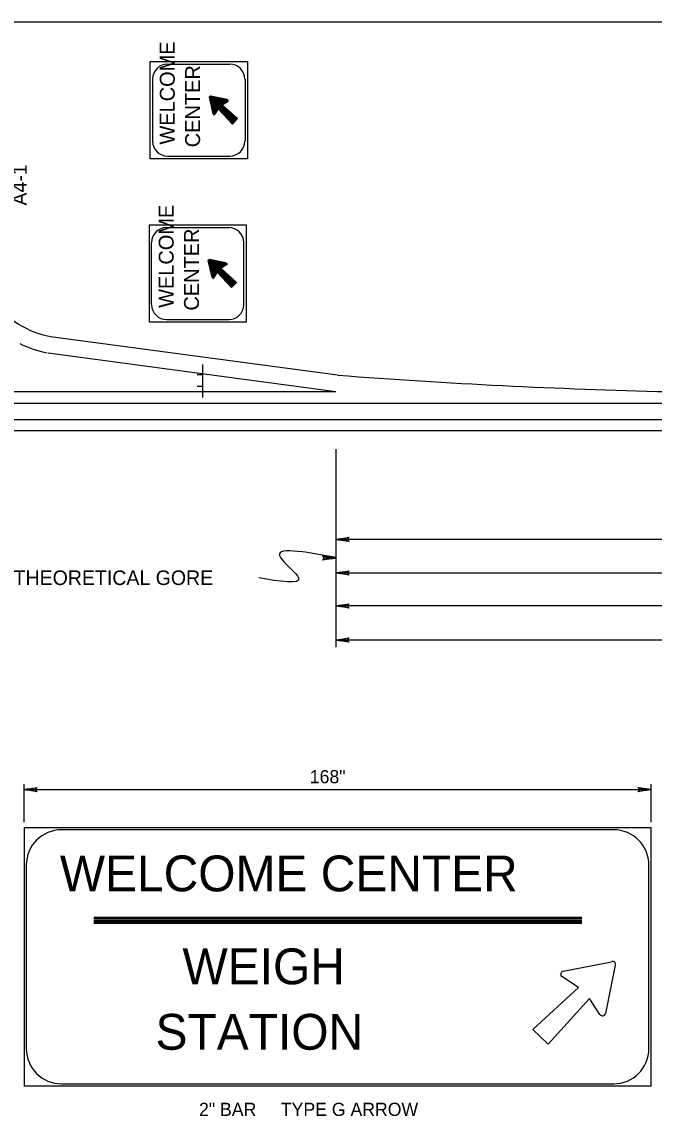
# Model space of a CAD drawing. Extents: x 638689 to 652291, y 298458 to 299646.
# Drawn here: x 651609.3 to 651753, y 298788 to 299036.7 of the extents above; entities that cross this region are included whole.
import ezdxf

# ---------------------------------------------------------------- set-up
doc = ezdxf.new("R2010")
doc.units = 0
for name, color, linetype in [('1', 7, 'Continuous'), ('2', 7, 'Continuous'), ('3', 7, 'Continuous')]:
    doc.layers.add(name, color=color, linetype=linetype)

# ---------------------------------------------------------------- blocks, each defined once
blk = doc.blocks.new('RARROW')
at = {"layer": '3'}
blk.add_lwpolyline([(-2.2695, 0.285), (-2.184875, 0.12075), (0, 0), (-2.2695, 0.285), (-2.38575, 0.384625), (0, 0), (-2.183125, -0.108), (-2.262875, -0.2705), (0, 0), (-2.38575, -0.379125), (-2.262875, -0.2705)], dxfattribs=at)

msp = doc.modelspace()

# ---------------------------------------------------------------- linework, layer by layer
at = {"layer": '1'}
msp.add_line((651426.31, 299036.75), (652212.31, 299036.75), dxfattribs=at)
at = {"layer": '2'}
for p, q in [((651642.44, 299027.12), (651656.56, 299027.12)), ((651651.81, 299019.87), (651651.81, 299019.87)), ((651655.94, 299019.12), (651652.19, 299019.87)), ((651651.94, 299019.62), (651652.81, 299015.87)), ((651654.81, 299017.87), (651656.19, 299018.75)), ((651654.81, 299017.87), (651654.81, 299017.87)), ((651658.31, 299014.75), (651654.81, 299017.87)), ((651656.56, 299019), (651656.56, 299019)), ((651652.94, 299015.37), (651652.94, 299015.37)), ((651653.19, 299015.75), (651653.94, 299017)), ((651653.94, 299017), (651653.94, 299017)), ((651653.94, 299017), (651657.19, 299013.5)), ((651657.19, 299013.5), (651658.31, 299014.75)), ((651660.56, 299005.62), (651638.44, 299005.62)), ((651656.56, 299006.12), (651642.44, 299006.12)), ((651642.19, 298990), (651656.44, 298990)), ((651651.56, 298982.75), (651651.56, 298982.75)), ((651651.69, 298982.5), (651652.56, 298978.75)), ((651655.69, 298982), (651651.94, 298982.75)), ((651652.94, 298978.62), (651653.69, 298979.87)), ((651653.69, 298979.87), (651653.69, 298979.87)), ((651653.69, 298979.87), (651656.94, 298976.37)), ((651654.56, 298980.75), (651655.81, 298981.62)), ((651654.56, 298980.75), (651654.56, 298980.75)), ((651658.06, 298977.5), (651654.56, 298980.75)), ((651656.31, 298981.87), (651656.31, 298981.87)), ((651652.69, 298978.25), (651652.69, 298978.25)), ((651656.94, 298976.37), (651658.06, 298977.5)), ((651660.31, 298968.5), (651638.31, 298968.5)), ((651656.44, 298969), (651642.19, 298969)), ((651615.81, 298965.25), (651681.06, 298956.5)), ((651615.31, 298961.5), (651615.31, 298961.5)), ((651615.31, 298961.5), (651680.69, 298952.75)), ((651650.44, 298951.37), (651650.44, 298958.87)), ((651650.44, 298956.5), (651649.19, 298956.5)), ((651441.81, 298952.75), (651680.69, 298952.75)), ((651650.44, 298953.87), (651649.19, 298953.87)), ((651680.69, 298952.75), (651680.69, 298952.75)), ((651680.69, 298952.75), (651680.69, 298952.75)), ((651429.31, 298950.12), (652211.31, 298950.12)), ((651429.31, 298946.37), (652211.31, 298946.37)), ((651429.31, 298943.87), (652211.31, 298943.87)), ((651680.69, 298939.62), (651680.69, 298894.62)), ((651917.06, 298919.12), (651680.69, 298919.12)), ((651680.69, 298911.5), (652031.94, 298911.5)), ((652084.69, 298904), (651680.69, 298904)), ((652137.56, 298896.25), (651680.69, 298896.25)), ((651609.82, 298854.87), (651609.82, 298863.49)), ((651752.32, 298854.87), (651752.32, 298863.49)), ((651609.82, 298862.24), (651752.32, 298862.24)), ((651609.82, 298853.62), (651752.32, 298853.62)), ((651609.82, 298853.62), (651609.82, 298794.87)), ((651743.82, 298853.12), (651618.32, 298853.12)), ((651752.32, 298794.87), (651752.32, 298853.62)), ((651610.32, 298845.12), (651610.32, 298803.37)), ((651751.82, 298803.37), (651751.82, 298845.12)), ((651625.69, 298833.24), (651736.57, 298833.24)), ((651625.69, 298832.99), (651736.57, 298832.99)), ((651625.69, 298832.62), (651736.57, 298832.62)), ((651625.69, 298832.37), (651736.57, 298832.37)), ((651625.69, 298832.12), (651736.57, 298832.12)), ((651625.69, 298831.87), (651736.57, 298831.87)), ((651744.32, 298823.37), (651744.32, 298823.37)), ((651732.32, 298820.99), (651743.32, 298823.12)), ((651744.19, 298822.37), (651741.94, 298811.37)), ((651744.19, 298822.37), (651741.94, 298811.37)), ((651730.82, 298820.62), (651730.82, 298820.62)), ((651735.82, 298817.24), (651732.07, 298819.74)), ((651735.82, 298817.24), (651732.07, 298819.74)), ((651725.44, 298807.74), (651735.82, 298817.24)), ((651725.44, 298807.74), (651735.82, 298817.24)), ((651735.82, 298817.24), (651735.82, 298817.24)), ((651737.07, 298815.99), (651737.07, 298815.99)), ((651738.32, 298814.74), (651728.94, 298804.37)), ((651738.32, 298814.74), (651728.94, 298804.37)), ((651740.69, 298811.12), (651738.32, 298814.74)), ((651738.32, 298814.74), (651738.32, 298814.74)), ((651741.69, 298809.87), (651741.69, 298809.87)), ((651728.94, 298804.37), (651725.44, 298807.74)), ((651728.94, 298804.37), (651725.44, 298807.74)), ((651725.44, 298807.74), (651725.44, 298807.74)), ((651728.94, 298804.37), (651728.94, 298804.37)), ((651752.32, 298794.87), (651609.82, 298794.87)), ((651618.32, 298795.37), (651743.82, 298795.37))]:
    msp.add_line(p, q, dxfattribs=at)
for points in [[(651638.44, 299005.62), (651638.44, 299027.75), (651640.69, 299027.75), (651644.06, 299027.75), (651646.44, 299027.75), (651649.81, 299027.75), (651651.81, 299027.75), (651658.44, 299027.75), (651660.56, 299027.75), (651660.56, 299027.75), (651660.56, 299005.62), (651660.56, 299005.62)], [(651639.06, 299009.62), (651639.06, 299023.75)], [(651660.06, 299023.75), (651660.06, 299009.62)], [(651657.19, 299013.5), (651653.94, 299017), (651653.19, 299015.75), (651652.94, 299015.75), (651652.81, 299015.87), (651651.94, 299019.62), (651652.06, 299019.75), (651652.19, 299019.87), (651655.94, 299019), (651656.19, 299018.87), (651655.94, 299018.75), (651654.69, 299017.87), (651658.31, 299014.75), (651657.19, 299013.5), (651653.94, 299017.12), (651653.06, 299015.75), (651652.94, 299015.75), (651652.94, 299015.87), (651652.06, 299019.62), (651652.06, 299019.75), (651652.19, 299019.75), (651655.94, 299019), (651655.94, 299018.87), (651655.94, 299018.75), (651654.69, 299017.87), (651658.19, 299014.75), (651657.19, 299013.62), (651653.94, 299017.12), (651653.06, 299015.87), (651652.94, 299015.87), (651652.94, 299015.87), (651652.06, 299019.75), (651655.94, 299018.87), (651654.56, 299017.87), (651658.06, 299014.62), (651657.19, 299013.75), (651653.94, 299017.25), (651652.94, 299015.87), (651652.19, 299019.62)], [(651653.06, 299016), (651652.19, 299019.75), (651655.94, 299018.87), (651654.44, 299017.87), (651658.06, 299014.62), (651657.19, 299013.75), (651653.94, 299017.25), (651653.06, 299016.12), (651652.44, 299019.62), (651655.81, 299018.87), (651654.44, 299017.87), (651657.94, 299014.62), (651657.19, 299013.87), (651653.94, 299017.37), (651653.06, 299016.25), (651652.44, 299019.5), (651655.56, 299018.75), (651654.31, 299017.87), (651657.81, 299014.62), (651657.19, 299014.12), (651653.94, 299017.37), (651653.19, 299016.5), (651652.56, 299019.37), (651655.31, 299018.75), (651654.19, 299017.87), (651657.69, 299014.75), (651657.19, 299014.12), (651653.94, 299017.5), (651653.19, 299016.75), (651652.69, 299019.25), (651655.19, 299018.75), (651654.06, 299017.87), (651657.56, 299014.75), (651657.19, 299014.25), (651653.94, 299017.62), (651653.19, 299016.87), (651652.81, 299019.12), (651654.94, 299018.62), (651654.06, 299017.87), (651657.44, 299014.75), (651657.44, 299014.75), (651657.19, 299014.5), (651653.81, 299017.62), (651653.31, 299017), (651652.94, 299019.12), (651654.81, 299018.62), (651653.94, 299017.87), (651657.31, 299014.62), (651657.19, 299014.62), (651653.94, 299017.75), (651653.31, 299017.25), (651652.94, 299019), (651654.56, 299018.62), (651653.94, 299017.87), (651657.31, 299014.62), (651657.19, 299014.62), (651653.94, 299017.87), (651653.44, 299017.37), (651653.06, 299018.87), (651654.56, 299018.5), (651653.44, 299017.5), (651653.19, 299018.75), (651654.31, 299018.5), (651653.44, 299017.62), (651653.31, 299018.62), (651654.19, 299018.5), (651653.44, 299017.75), (651653.31, 299018.62), (651654.06, 299018.37), (651653.56, 299018), (651653.44, 299018.5), (651653.81, 299018.37), (651653.56, 299018.25), (651653.56, 299018.37), (651653.69, 299018.37)], [(651638.31, 298968.5), (651638.31, 298990.62), (651640.44, 298990.62), (651643.81, 298990.62), (651646.19, 298990.62), (651649.56, 298990.62), (651651.56, 298990.62), (651658.19, 298990.62), (651660.31, 298990.62), (651660.31, 298990.62), (651660.31, 298968.5), (651660.31, 298968.5)], [(651638.81, 298972.5), (651638.81, 298986.62)], [(651659.69, 298986.62), (651659.69, 298972.5)], [(651656.94, 298976.37), (651653.69, 298979.87), (651652.94, 298978.62), (651652.81, 298978.62), (651652.56, 298978.75), (651651.69, 298982.5), (651651.81, 298982.62), (651651.94, 298982.75), (651655.69, 298981.87), (651655.81, 298981.75), (651655.81, 298981.62), (651654.56, 298980.75), (651658.06, 298977.5), (651656.94, 298976.37), (651653.69, 298980), (651652.81, 298978.62), (651652.81, 298978.62), (651652.69, 298978.75), (651651.81, 298982.5), (651651.81, 298982.62), (651651.94, 298982.62), (651655.69, 298981.87), (651655.81, 298981.75), (651655.69, 298981.62), (651654.44, 298980.75), (651657.94, 298977.5), (651656.94, 298976.5), (651653.69, 298980), (651652.81, 298978.75), (651652.69, 298978.75), (651652.69, 298978.75), (651651.81, 298982.62), (651655.69, 298981.75), (651654.44, 298980.75), (651657.94, 298977.37), (651656.94, 298976.62), (651653.69, 298980), (651652.81, 298978.75), (651651.94, 298982.5)], [(651652.81, 298978.87), (651651.94, 298982.62), (651655.69, 298981.75), (651654.31, 298980.75), (651657.81, 298977.37), (651656.94, 298976.62), (651653.69, 298980.12), (651652.81, 298979), (651652.06, 298982.5), (651655.56, 298981.75), (651654.19, 298980.75), (651657.81, 298977.37), (651656.94, 298976.75), (651653.69, 298980.25), (651652.94, 298979.12), (651652.06, 298982.37), (651655.31, 298981.62), (651654.06, 298980.75), (651657.69, 298977.37), (651656.94, 298976.87), (651653.69, 298980.25), (651652.94, 298979.37), (651652.19, 298982.25), (651655.06, 298981.62), (651653.94, 298980.75), (651657.44, 298977.37), (651656.94, 298977), (651653.69, 298980.37), (651652.94, 298979.62), (651652.44, 298982.12), (651654.94, 298981.62), (651653.94, 298980.75), (651657.31, 298977.37), (651656.94, 298977.12), (651653.69, 298980.5), (651653.06, 298979.75), (651652.56, 298982), (651654.69, 298981.37), (651653.81, 298980.75), (651657.19, 298977.5), (651657.19, 298977.5), (651656.94, 298977.25), (651653.69, 298980.5), (651653.06, 298979.87), (651652.69, 298982), (651654.56, 298981.37), (651653.81, 298980.75), (651657.19, 298977.37), (651656.94, 298977.37), (651653.69, 298980.62), (651653.06, 298980.12), (651652.69, 298981.87), (651654.44, 298981.37), (651653.69, 298980.75), (651657.06, 298977.37), (651656.94, 298977.37), (651653.69, 298980.75), (651653.19, 298980.25), (651652.81, 298981.75), (651654.31, 298981.25), (651653.19, 298980.37), (651652.94, 298981.62), (651654.19, 298981.25), (651653.19, 298980.5), (651653.06, 298981.37), (651654.06, 298981.25), (651653.31, 298980.62), (651653.19, 298981.37), (651653.81, 298981.12), (651653.31, 298980.87), (651653.19, 298981.25), (651653.69, 298981.12), (651653.44, 298981), (651653.31, 298981.12), (651653.44, 298981.12)]]:
    msp.add_lwpolyline(points, dxfattribs=at)
for centre, radius, start, end in [((651642.43, 299023.76), 3.39, 90, 180), ((651656.57, 299023.76), 3.39, 0, 90), ((651652.18, 299019.66), 0.212, 78.0958, 191.9043), ((651652.18, 299019.66), 0.212, 78.0958, 191.9043), ((651655.98, 299018.86), 0.212, 302.692, 78.0958), ((651655.98, 299018.86), 0.212, 302.692, 78.0958), ((651652.98, 299015.86), 0.212, 191.9042, 327.308), ((651652.98, 299015.86), 0.212, 191.9043, 327.308), ((651642.43, 299009.62), 3.39, 180, 270), ((651656.57, 299009.62), 3.39, 270, 0), ((651642.2, 298986.61), 3.39, 90, 180), ((651656.34, 298986.61), 3.39, 0, 90), ((651651.95, 298982.51), 0.212, 78.0958, 191.9043), ((651651.95, 298982.51), 0.212, 78.0958, 191.9043), ((651655.75, 298981.71), 0.212, 302.692, 78.0958), ((651655.75, 298981.71), 0.212, 302.692, 78.0958), ((651652.75, 298978.71), 0.212, 191.9042, 327.308), ((651652.75, 298978.71), 0.212, 191.9043, 327.308), ((651619.81, 298986.34), 21.48, 217.6891, 259.2048), ((651642.2, 298972.47), 3.39, 180, 270), ((651656.34, 298972.47), 3.39, 270, 0), ((651619.81, 298986.34), 25.25, 244.1957, 259.2048), ((651789.98, 300385.53), 1433.22, 265.6447, 268.64351), ((651618.32, 298845.12), 8, 90, 180), ((651743.82, 298845.12), 8, 0, 90), ((651743.57, 298822.52), 0.686, 348.2602, 101.7398), ((651743.57, 298822.52), 0.686, 348.2602, 101.7398), ((651732.44, 298820.3), 0.675, 101.0564, 236.3099), ((651741.28, 298811.5), 0.686, 213.3162, 348.2602), ((651741.28, 298811.5), 0.686, 213.3162, 348.2602), ((651618.32, 298803.37), 8, 180, 270), ((651743.82, 298803.37), 8, 270, 0)]:
    msp.add_arc(centre, radius, start, end, dxfattribs=at)
msp.add_spline([(651680.69, 298915), (651668.06, 298915), (651672.19, 298910.37), (651663.15, 298910.37)], degree=3, dxfattribs=at)

# ---------------------------------------------------------------- block references
at = {"layer": '2', "xscale": 1.2574347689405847, "yscale": 1.3092961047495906, "rotation": 180}
for p in [(651680.69, 298919.12), (651680.69, 298911.5), (651680.69, 298904), (651680.69, 298896.25), (651609.82, 298862.24)]:
    msp.add_blockref('RARROW', p, dxfattribs=at)
at = {"layer": '2', "xscale": 1.2574347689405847, "yscale": 1.3092961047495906}
for p in [(651680.63, 298914.88), (651752.32, 298862.24)]:
    msp.add_blockref('RARROW', p, dxfattribs=at)

# ---------------------------------------------------------------- texts
at = {"layer": '2'}
for s, height, p in [('WELCOME', 3.392, (651644.06, 299008.87)), ('CENTER', 3.392, (651649.81, 299008.25)), ('A4-1', 3.318, (651610.44, 298995)), ('WELCOME', 3.392, (651643.81, 298971.75)), ('CENTER', 3.392, (651649.56, 298971.12))]:
    msp.add_text(s, height=height, rotation=90, dxfattribs=at).set_placement(p)
for s, height, p in [('THEORETICAL GORE', 3.3173, (651607.44, 298908.75)), ('168"', 3, (651674.75, 298863.69)), ('WELCOME CENTER', 8.1435, (651617.94, 298839.12)), ('WEIGH', 8.143, (651645.82, 298817.99)), ('STATION', 8.143, (651639.69, 298803.12)), ('2" BAR     TYPE G ARROW', 3, (651649.58, 298788.07))]:
    msp.add_text(s, height=height, dxfattribs=at).set_placement(p)

doc.saveas('drawing.dxf')
